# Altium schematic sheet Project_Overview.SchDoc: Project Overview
size A4; Date: Not used; ApprovedBy: Not used; CheckedBy: Not used; Author: Not used; CompanyName: STMicroelectronics; DrawnBy: Not used; Engineer: Not used; Organization: Not used; Address1: Not used; Address2: Not used; Address3: Not used; Address4: Not used; DocumentNumber: Not used; Revision: Not used; SheetNumber: 1; SheetTotal: 4
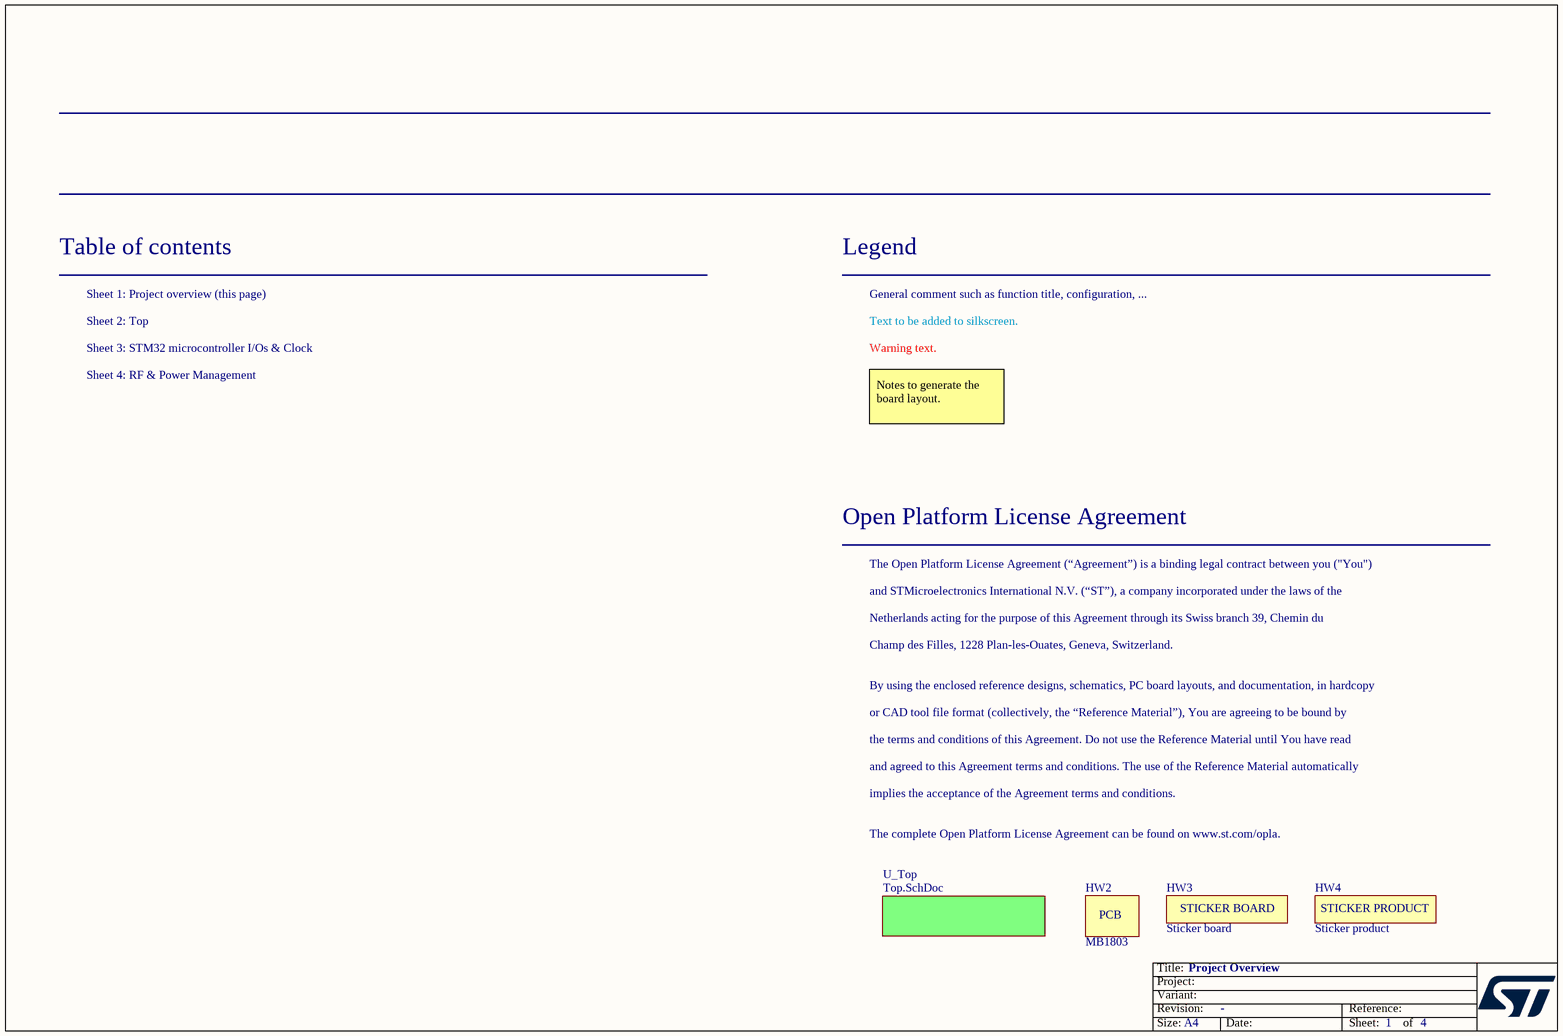
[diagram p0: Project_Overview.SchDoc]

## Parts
HW2  value MB1803  (hidden comment: PCB)  (no BOM)
HW3  value Sticker board  [STICKER_BOARD_25X5]  (hidden comment: STICKER_BOARD)  (no BOM)
HW4  value Sticker product  [STICKER_PRODUCT_25X5]  (hidden comment: STICKER_PRODUCT)  (no BOM)

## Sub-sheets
U_Top = Top.SchDoc: no entries

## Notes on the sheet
- Table of contents
- Sheet 1: Project overview (this page)
- Legend
- General comment such as function title, configuration, ...
- Sheet 2: Top
- Sheet 3: STM32 microcontroller I/Os & Clock
- Sheet 4: RF & Power Management
- Text to be added to silkscreen.
- Warning text.
- Notes to generate the board layout.
- Open Platform License Agreement
- The Open Platform License Agreement (“Agreement”) is a binding legal contract between you ("You")
- and STMicroelectronics International N.V. (“ST”), a company incorporated under the laws of the
- Netherlands acting for the purpose of this Agreement through its Swiss branch 39, Chemin du
- Champ des Filles, 1228 Plan-les-Ouates, Geneva, Switzerland.
- By using the enclosed reference designs, schematics, PC board layouts, and documentation, in hardcopy
- or CAD tool file format (collectively, the “Reference Material”), You are agreeing to be bound by
- the terms and conditions of this Agreement. Do not use the Reference Material until You have read
- and agreed to this Agreement terms and conditions. The use of the Reference Material automatically
- implies the acceptance of the Agreement terms and conditions.
- The complete Open Platform License Agreement can be found on www.st.com/opla.

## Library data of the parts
HW2 = MCD-02991: PCB MB1803, 4L2S of MiniBoard for STM32WBA55, QFN48, SMPS, PCB Antenna.; Part_Preference: Recommended; Manufacturer: PLOTEC; ShowFields: YES; ID: 5107; Component_Country_Of_Origin: Unknown
HW3 = MCD-02190: Sticker board 25x5 mm; Part_Type: Misc; Part_Preference: Recommended
HW4 = MCD-02189: Sticker product 25x5 mm; Part_Type: Misc; Part_Preference: Recommended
